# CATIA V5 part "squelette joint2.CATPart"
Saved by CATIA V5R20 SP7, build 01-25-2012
Part number: squelette joint2
Publications: "Droite.3", "Plan.1", "Plan.2", "Plan.3", "Point.1", "Droite.2", "Point.4", "Droite.1", "rayon plus grand", "longeur du poche plus petit", "rayon plus petit", "epaisseur du joint"
Bounding box of the stored display mesh (mm): x -166.695 to 0, y -40 to 0, z 0 to 0
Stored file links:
  D:\thinkmotion-MPB\Dropbox\Pack 1 sylvain\yyang\yyang\yyang\squelette joint2.CATPart
  D:\thinkmotion-MPB\Dropbox\Pack 1 sylvain\yyang\yyang\yyang\yyang.CATProduct
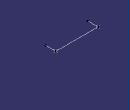
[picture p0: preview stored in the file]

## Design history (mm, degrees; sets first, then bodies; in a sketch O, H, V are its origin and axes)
Parameters
  `rayon plus grand` = 18 mm
  `longeur du poche plus petit` = 20 mm
  `rayon plus petit` = 11 mm
  `epaisseur du joint` = 3 mm
Set1
  Point1: linked copy from another document
  Point2: linked copy from another document
Body1 (main body)
  Plane1: type Offset, RefPlane xy-plane, Offset 0
  Plane2: type Offset, RefPlane yz-plane, Offset 0
  Plane3: type Offset, RefPlane zx-plane, Offset 0
  Point3: (0, 0, 0)
  Line1: type PtDir, RefPoint Point3, Direction (0, 1, 0), Start 0, End 40
  Line2: type PtDir, RefPoint Point3, Direction (1, 0, 0), Start 0, End 166.6953 {= distance(Point2,Point1)+0.1mm}
  Point4: (0, 0, 0), relative to vertex of Line2
  Line3: type PtDir, RefPoint Point4, Direction (0, 1, 0), Start 0, End 40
